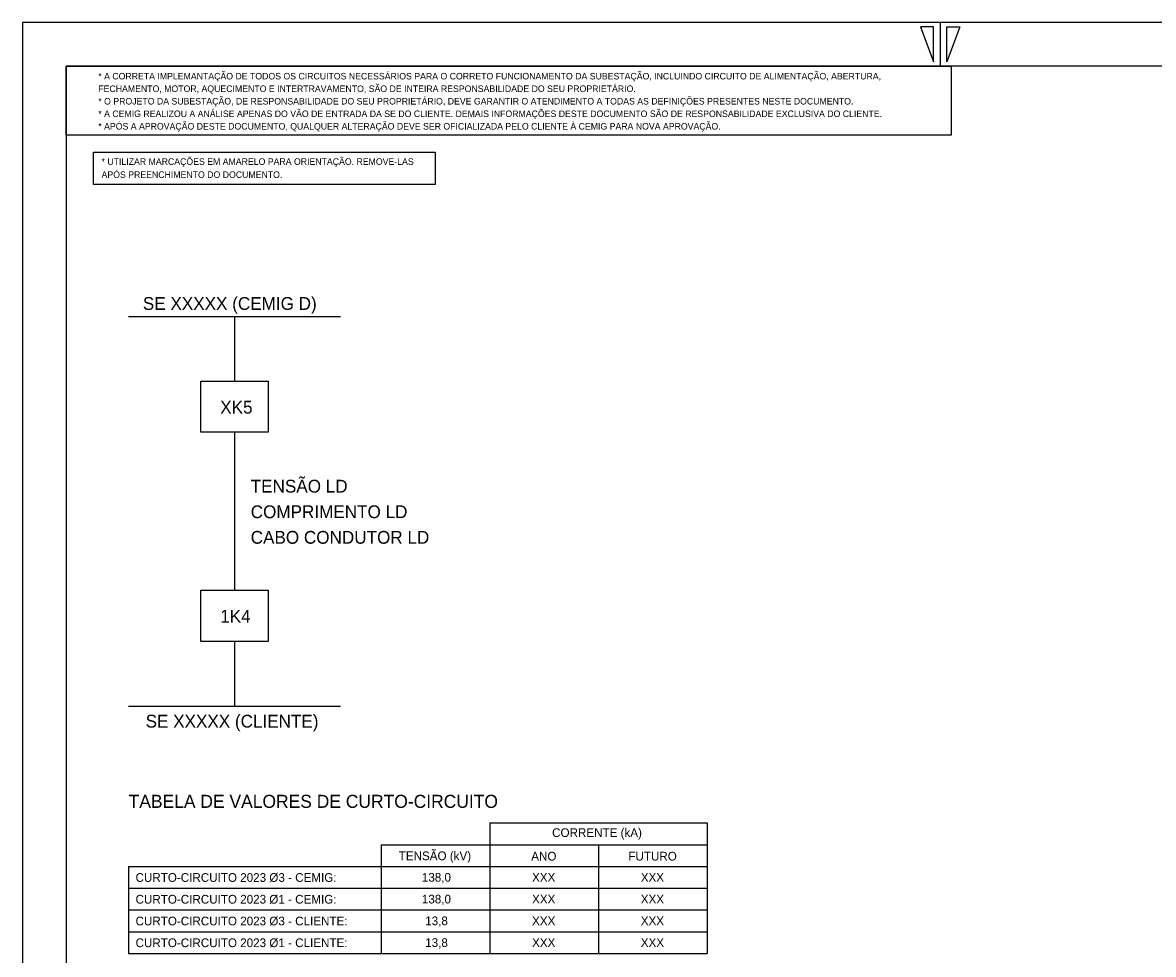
# Model space of a CAD drawing. Extents: x 563 to 1404, y 358 to 952.
# Drawn here: x 562.6 to 822.6, y 737.8 to 952 of the extents above; entities that cross this region are included whole.
import ezdxf

# ---------------------------------------------------------------- set-up
doc = ezdxf.new("R2010")
doc.units = 0
doc.layers.add('New Level (0)', color=7, linetype='Continuous')

# ---------------------------------------------------------------- blocks, each defined once
blk = doc.blocks.new('POINT_DISPLAY')
blk.add_line((0, 0), (0, 0))

msp = doc.modelspace()

# ---------------------------------------------------------------- linework, layer by layer
for p, q in [((586.96, 884.4), (635.66, 884.4)), ((611.31, 884.4), (611.31, 869.54)), ((611.31, 857.81), (611.31, 821.5)), ((611.31, 809.77), (611.31, 794.9)), ((586.96, 794.9), (635.66, 794.9))]:
    msp.add_line(p, q)
for points in [[(603.54, 869.54), (619.08, 869.54), (619.08, 857.81), (603.54, 857.81)], [(603.54, 821.5), (619.08, 821.5), (619.08, 809.77), (603.54, 809.77)]]:
    msp.add_lwpolyline(points, close=True)
at = {"layer": 'New Level (0)'}
for p, q in [((562.58, 951.96), (562.58, 357.96)), ((1403.58, 951.96), (562.58, 951.96)), ((1403.58, 951.96), (562.58, 951.96)), ((562.58, 951.96), (562.58, 357.96)), ((773.58, 951.96), (773.58, 941.96)), ((772.08, 950.96), (769.08, 950.96)), ((769.08, 950.96), (772.08, 942.96)), ((772.08, 942.96), (772.08, 950.96)), ((775.08, 942.96), (775.08, 950.96)), ((775.08, 950.96), (778.08, 950.96)), ((778.08, 950.96), (775.08, 942.96)), ((572.58, 941.96), (572.58, 367.96)), ((1393.58, 941.96), (572.58, 941.96)), ((572.58, 941.96), (572.58, 367.96)), ((670.01, 768.04), (670.01, 738.04)), ((670.01, 768.04), (720.01, 768.04)), ((720.01, 768.04), (720.01, 738.04)), ((645.01, 763.04), (645.01, 738.04)), ((645.01, 763.04), (720.01, 763.04)), ((695.01, 763.04), (695.01, 738.04)), ((586.96, 758.04), (720.01, 758.04)), ((586.96, 758.04), (586.96, 738.04)), ((586.96, 753.04), (720.01, 753.04)), ((586.96, 748.04), (720.01, 748.04)), ((586.96, 743.04), (720.01, 743.04)), ((586.96, 738.04), (720.01, 738.04))]:
    msp.add_line(p, q, dxfattribs=at)
for points in [[(572.58, 941.96), (776.08, 941.96), (776.08, 926.09), (572.58, 926.09)], [(578.87, 922.15), (657.43, 922.15), (657.43, 914.73), (578.87, 914.73)]]:
    msp.add_lwpolyline(points, close=True, dxfattribs=at)

# ---------------------------------------------------------------- block references
msp.add_blockref('POINT_DISPLAY', (670.01, 758.04), dxfattribs=at)

# ---------------------------------------------------------------- texts
for s, height, p in [('* UTILIZAR MARCAÇÕES EM AMARELO PARA ORIENTAÇÃO. REMOVE-LAS ', 1.5, (580.73, 919.27)), ('APÓS PREENCHIMENTO DO DOCUMENTO.', 1.5, (580.73, 916.27)), ('SE XXXXX (CEMIG D)', 2.94, (590.23, 885.94)), ('XK5', 2.94, (608.02, 862.11)), ('TENSÃO LD ', 2.94, (615.03, 843.96)), ('COMPRIMENTO LD', 2.94, (615.03, 838.08)), ('CABO CONDUTOR LD ', 2.94, (615.03, 832.2)), ('1K4', 2.94, (608.02, 814.07)), ('SE XXXXX (CLIENTE)', 2.94, (590.86, 789.95)), ('TABELA DE VALORES DE CURTO-CIRCUITO', 3, (586.96, 771.5)), ('CORRENTE (kA)', 2, (684.34, 764.81)), ('TENSÃO (kV)', 2, (649.07, 759.48)), ('ANO', 2, (679.54, 759.4)), ('FUTURO', 2, (701.87, 759.4)), ('CURTO-CIRCUITO 2023 Ø3 - CEMIG:', 2, (588.55, 754.5)), ('138,0', 2, (654.39, 754.54)), ('XXX', 2, (679.73, 754.54)), ('XXX', 2, (704.73, 754.54)), ('CURTO-CIRCUITO 2023 Ø1 - CEMIG:', 2, (588.55, 749.5)), ('138,0', 2, (654.39, 749.54)), ('XXX', 2, (679.73, 749.54)), ('XXX', 2, (704.73, 749.54)), ('CURTO-CIRCUITO 2023 Ø3 - CLIENTE:', 2, (588.55, 744.5)), ('13,8', 2, (655.16, 744.54)), ('XXX', 2, (679.73, 744.54)), ('XXX', 2, (704.73, 744.54)), ('CURTO-CIRCUITO 2023 Ø1 - CLIENTE:', 2, (588.55, 739.5)), ('13,8', 2, (655.16, 739.54)), ('XXX', 2, (679.73, 739.54)), ('XXX', 2, (704.73, 739.54))]:
    msp.add_text(s, height=height).set_placement(p)
for s, p in [('* A CORRETA IMPLEMANTAÇÃO DE TODOS OS CIRCUITOS NECESSÁRIOS PARA O CORRETO FUNCIONAMENTO DA SUBESTAÇÃO, INCLUINDO CIRCUITO DE ALIMENTAÇÃO, ABERTURA,   ', (579.98, 938.9)), ('FECHAMENTO, MOTOR, AQUECIMENTO E INTERTRAVAMENTO, SÃO DE INTEIRA RESPONSABILIDADE DO SEU PROPRIETÁRIO.', (579.98, 936.02)), ('* O PROJETO DA SUBESTAÇÃO, DE RESPONSABILIDADE DO SEU PROPRIETÁRIO, DEVE GARANTIR O ATENDIMENTO A TODAS AS DEFINIÇÕES PRESENTES NESTE DOCUMENTO.', (579.98, 933.14)), ('* A CEMIG REALIZOU A ANÁLISE APENAS DO VÃO DE ENTRADA DA SE DO CLIENTE. DEMAIS INFORMAÇÕES DESTE DOCUMENTO SÃO DE RESPONSABILIDADE EXCLUSIVA DO CLIENTE.', (579.98, 930.26)), ('* APÓS A APROVAÇÃO DESTE DOCUMENTO, QUALQUER ALTERAÇÃO DEVE SER OFICIALIZADA PELO CLIENTE À CEMIG PARA NOVA APROVAÇÃO.', (579.98, 927.38))]:
    msp.add_text(s, height=1.5, dxfattribs=at).set_placement(p)

doc.saveas('drawing.dxf')
